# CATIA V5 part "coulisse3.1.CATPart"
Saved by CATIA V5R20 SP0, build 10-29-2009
Part number: coulisse3.1
Bounding box of the stored display mesh (mm): x 0 to 5, y -11 to 52.777, z -10.989 to 374.074
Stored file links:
  C:\Users\thinkmotion1\Desktop\IAO OK\IAO_2010_1458_splanchena\Correction_Khaled\coulisse3.1.CATPart
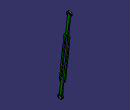
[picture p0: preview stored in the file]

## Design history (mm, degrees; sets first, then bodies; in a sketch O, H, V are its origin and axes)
Body1 (main body)
  Sketch1 on yz-plane, origin (0, 0, 0), H (0, 1, 0), V (0, 0, 1)
    arc A1 centre (0, 0) radius 11 from (-4.2256, 10.156) to (7.234, 8.2867) ccw
    circle A2 centre (0, 0) radius 7.5
    arc A3 centre (41.7775, 363.0833) radius 11 from (46.1972, 353.0102) to (35.4667, 354.0736) ccw
    circle A4 centre (41.7775, 363.0833) radius 6
    line L1 (35.4667, 354.0736) -> (26.2146, 277.2147)
    line L2 (46.1972, 353.0102) -> (37.0543, 277.0586)
    line L3 (37.0543, 277.0586) -> (43.3055, 266.0245)
    line L4 (26.2146, 277.2147) -> (18.3829, 268.1227)
    line L5 (43.3055, 266.0245) -> (20.9135, 69.2948)
    line L6 (18.3829, 268.1227) -> (-4.0091, 71.3929)
    line L7 (20.9135, 69.2948) -> (13.1377, 60.1549)
    line L8 (-4.0091, 71.3929) -> (1.5331, 60.7494)
    line L9 (13.1377, 60.1549) -> (7.234, 8.2867)
    line L10 (1.5331, 60.7494) -> (-4.2256, 10.156)
    line L11 (36.9135, 265.693) -> (14.2583, 70)
    point P14 (14.2583, 70)
    line L12 (24.9757, 266.923) -> (2.2839, 70.9137)
    point P16 (24.9757, 266.923)
    arc A5 centre (30.9369, 266.2329) radius 6.0009 from (24.9757, 266.923) to (36.9135, 265.693) cw
    arc A6 centre (8.2881, 70.6795) radius 6.0087 from (2.2839, 70.9137) to (14.2583, 70) ccw
    radius A1 = 11
    radius A2 = 7.5
    radius A3 = 11
    radius A4 = 6
    length L2 = 76.5
    distance L6 L5 = 25
    length L8 = 12
    length L11 = 197
    length L12 = 197.3185
    distance L12 L11 = 12
    parallelism: L9 L5, L10 L6
    coincidence: P14 L9, P16 L1
    tangency: A5 L12, A6 L9
  Pad1: profile Sketch1, direction (1, 0, 0), length 5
